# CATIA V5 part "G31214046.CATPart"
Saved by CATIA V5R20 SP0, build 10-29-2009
Part number: G31214046
Revision: 4
Definition: design
Nomenclature: G31214046
Source: made
Description: NOT SPECIFIED
Bounding box of the stored display mesh (mm): x -6 to 46, y -12.31 to 12.31, z -12.5 to 12.5
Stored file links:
  C:\Users\Raffaele\Desktop\3D X SITO CF\BOLEX\23-BUSH REF 312\G31214046.CATPart

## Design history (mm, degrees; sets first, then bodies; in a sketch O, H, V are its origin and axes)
Body1 "MANIFOLD_SOLID_BREP #10219" (main body)
  Solid1: solid without history
Body2 "MANIFOLD_SOLID_BREP #10362"
  Solid2: solid without history
Body3 "MANIFOLD_SOLID_BREP #10505"
  Solid3: solid without history
Body4 "MANIFOLD_SOLID_BREP #10648"
  Solid4: solid without history
Body5 "MANIFOLD_SOLID_BREP #10791"
  Solid5: solid without history
Body6 "MANIFOLD_SOLID_BREP #10936"
  Solid6: solid without history
Body7 "MANIFOLD_SOLID_BREP #11081"
  Solid7: solid without history
Body8 "MANIFOLD_SOLID_BREP #11226"
  Solid8: solid without history
Body9 "MANIFOLD_SOLID_BREP #11371"
  Solid9: solid without history
Body10 "MANIFOLD_SOLID_BREP #11516"
  Solid10: solid without history
Body11 "MANIFOLD_SOLID_BREP #11661"
  Solid11: solid without history
Body12 "MANIFOLD_SOLID_BREP #11806"
  Solid12: solid without history
Body13 "MANIFOLD_SOLID_BREP #11951"
  Solid13: solid without history
Body14 "MANIFOLD_SOLID_BREP #12096"
  Solid14: solid without history
Body15 "MANIFOLD_SOLID_BREP #12241"
  Solid15: solid without history
Body16 "MANIFOLD_SOLID_BREP #12386"
  Solid16: solid without history
Body17 "MANIFOLD_SOLID_BREP #12531"
  Solid17: solid without history
Body18 "MANIFOLD_SOLID_BREP #12676"
  Solid18: solid without history
Body19 "MANIFOLD_SOLID_BREP #12821"
  Solid19: solid without history
Body20 "MANIFOLD_SOLID_BREP #12966"
  Solid20: solid without history
Body21 "MANIFOLD_SOLID_BREP #13111"
  Solid21: solid without history
Body22 "MANIFOLD_SOLID_BREP #13256"
  Solid22: solid without history
Body23 "MANIFOLD_SOLID_BREP #13401"
  Solid23: solid without history
Body24 "MANIFOLD_SOLID_BREP #13546"
  Solid24: solid without history
Body25 "MANIFOLD_SOLID_BREP #13691"
  Solid25: solid without history
Body26 "MANIFOLD_SOLID_BREP #13836"
  Solid26: solid without history
Body27 "MANIFOLD_SOLID_BREP #13981"
  Solid27: solid without history
Body28 "MANIFOLD_SOLID_BREP #14126"
  Solid28: solid without history
Body29 "MANIFOLD_SOLID_BREP #14271"
  Solid29: solid without history
Body30 "MANIFOLD_SOLID_BREP #14416"
  Solid30: solid without history
Body31 "MANIFOLD_SOLID_BREP #14561"
  Solid31: solid without history
Body32 "MANIFOLD_SOLID_BREP #14704"
  Solid32: solid without history
Body33 "MANIFOLD_SOLID_BREP #14847"
  Solid33: solid without history
Body34 "MANIFOLD_SOLID_BREP #14992"
  Solid34: solid without history
Body35 "MANIFOLD_SOLID_BREP #15137"
  Solid35: solid without history
Body36 "MANIFOLD_SOLID_BREP #15282"
  Solid36: solid without history
Body37 "MANIFOLD_SOLID_BREP #15427"
  Solid37: solid without history
Body38 "MANIFOLD_SOLID_BREP #15572"
  Solid38: solid without history
Body39 "MANIFOLD_SOLID_BREP #15717"
  Solid39: solid without history
Body40 "MANIFOLD_SOLID_BREP #15862"
  Solid40: solid without history
Body41 "MANIFOLD_SOLID_BREP #16007"
  Solid41: solid without history
Body42 "MANIFOLD_SOLID_BREP #16152"
  Solid42: solid without history
Body43 "MANIFOLD_SOLID_BREP #16297"
  Solid43: solid without history
Body44 "MANIFOLD_SOLID_BREP #16442"
  Solid44: solid without history
Body45 "MANIFOLD_SOLID_BREP #16587"
  Solid45: solid without history
Body46 "MANIFOLD_SOLID_BREP #16732"
  Solid46: solid without history
Body47 "MANIFOLD_SOLID_BREP #16877"
  Solid47: solid without history
Body48 "MANIFOLD_SOLID_BREP #17022"
  Solid48: solid without history
Body49 "MANIFOLD_SOLID_BREP #17167"
  Solid49: solid without history
Body50 "MANIFOLD_SOLID_BREP #17312"
  Solid50: solid without history
Body51 "MANIFOLD_SOLID_BREP #17457"
  Solid51: solid without history
Body52 "MANIFOLD_SOLID_BREP #17602"
  Solid52: solid without history
Body53 "MANIFOLD_SOLID_BREP #17747"
  Solid53: solid without history
Body54 "MANIFOLD_SOLID_BREP #17892"
  Solid54: solid without history
Body55 "MANIFOLD_SOLID_BREP #18037"
  Solid55: solid without history
Body56 "MANIFOLD_SOLID_BREP #18180"
  Solid56: solid without history
Body57 "MANIFOLD_SOLID_BREP #18323"
  Solid57: solid without history
Body58 "MANIFOLD_SOLID_BREP #18468"
  Solid58: solid without history
Body59 "MANIFOLD_SOLID_BREP #18613"
  Solid59: solid without history
Body60 "MANIFOLD_SOLID_BREP #18758"
  Solid60: solid without history
Body61 "MANIFOLD_SOLID_BREP #18903"
  Solid61: solid without history
Body62 "MANIFOLD_SOLID_BREP #19048"
  Solid62: solid without history
Body63 "MANIFOLD_SOLID_BREP #19193"
  Solid63: solid without history
Body64 "MANIFOLD_SOLID_BREP #19336"
  Solid64: solid without history
Body65 "MANIFOLD_SOLID_BREP #19479"
  Solid65: solid without history
Body66 "MANIFOLD_SOLID_BREP #19624"
  Solid66: solid without history
Body67 "MANIFOLD_SOLID_BREP #19769"
  Solid67: solid without history
Body68 "MANIFOLD_SOLID_BREP #19914"
  Solid68: solid without history
Body69 "MANIFOLD_SOLID_BREP #20059"
  Solid69: solid without history
Body70 "MANIFOLD_SOLID_BREP #20204"
  Solid70: solid without history
Body71 "MANIFOLD_SOLID_BREP #20349"
  Solid71: solid without history
Body72 "MANIFOLD_SOLID_BREP #20494"
  Solid72: solid without history
Body73 "MANIFOLD_SOLID_BREP #20639"
  Solid73: solid without history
